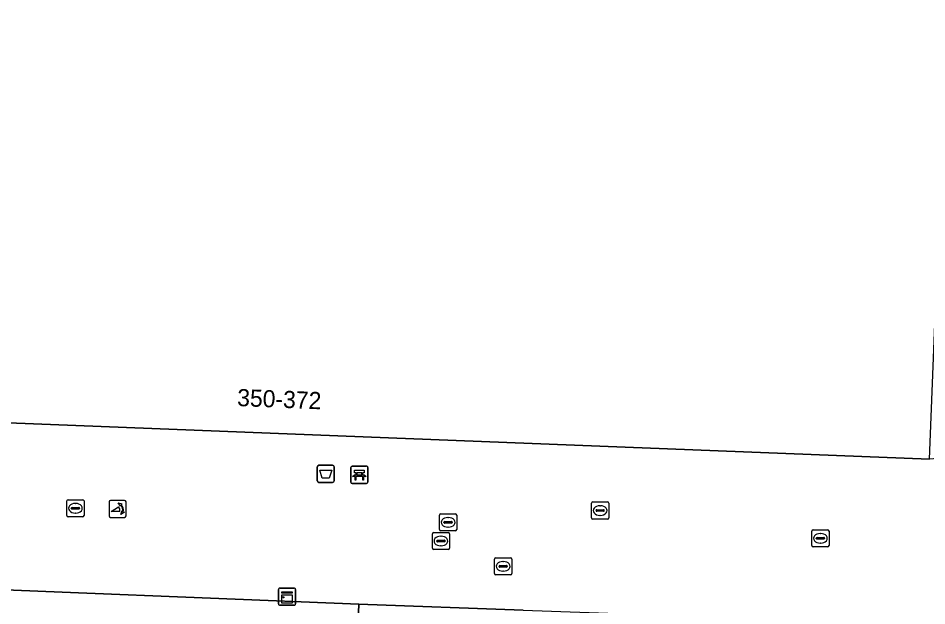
# Model space of a CAD drawing. Extents: x 160888 to 161385, y 386490 to 386908.
# Drawn here: x 161141.4 to 161194.4, y 386833.9 to 386868.1 of the extents above; entities that cross this region are included whole.
import ezdxf

# ---------------------------------------------------------------- set-up
doc = ezdxf.new("R2010")
doc.units = 0
for name, color, linetype in [('IMGEO_Afvalbak', 7, 'Continuous'), ('IMGEO_Bank', 7, 'Continuous'), ('IMGEO_Brandkraan', 7, 'Continuous'), ('IMGEO_Kast', 7, 'Continuous'), ('IMGEO_Kolk', 7, 'Continuous'), ('IMGEO_Pand', 7, 'Continuous'), ('IMGEO_Pand_nummerreeks', 7, 'Continuous'), ('IMGEO_Poller', 7, 'Continuous'), ('IMGEO_Rioolput', 7, 'Continuous'), ('IMGEO_Voetgangersgebied_open', 7, 'Continuous'), ('IMGEO_Voetpad_open', 7, 'Continuous')]:
    doc.layers.add(name, color=color, linetype=linetype)

msp = doc.modelspace()

# ---------------------------------------------------------------- linework, layer by layer
at = {"layer": 'IMGEO_Afvalbak'}
for p, q in [((161158.851, 386841.169), (161158.851, 386841.969)), ((161158.851, 386841.969), (161158.851, 386841.169)), ((161158.951, 386842.069), (161159.741, 386842.069)), ((161159.741, 386842.069), (161158.951, 386842.069)), ((161159.841, 386841.969), (161159.841, 386841.169)), ((161159.841, 386841.169), (161159.841, 386841.969)), ((161159.741, 386841.069), (161158.951, 386841.069)), ((161158.951, 386841.069), (161159.741, 386841.069))]:
    msp.add_line(p, q, dxfattribs=at)
msp.add_lwpolyline([(161158.994, 386841.783), (161159.698, 386841.783), (161159.549, 386841.313), (161159.143, 386841.313), (161158.994, 386841.783)], dxfattribs=at)
for centre, start, end in [((161158.951, 386841.969), 90, 180), ((161158.951, 386841.969), 90, 180), ((161159.741, 386841.969), 0, 90), ((161159.741, 386841.969), 360, 90), ((161158.951, 386841.169), 180, 270), ((161158.951, 386841.169), 180, 270), ((161159.741, 386841.169), 270, 0), ((161159.741, 386841.169), 270, 0)]:
    msp.add_arc(centre, 0.1, start, end, dxfattribs=at)
at = {"layer": 'IMGEO_Bank'}
for p, q in [((161160.805, 386841.088), (161160.805, 386841.929)), ((161160.805, 386841.929), (161160.805, 386841.088)), ((161160.88, 386842.013), (161161.721, 386842.013)), ((161161.721, 386842.013), (161160.88, 386842.013)), ((161161.446, 386841.631), (161161.164, 386841.631)), ((161161.805, 386841.938), (161161.805, 386841.097)), ((161161.805, 386841.097), (161161.805, 386841.938)), ((161161.502, 386841.411), (161161.109, 386841.411)), ((161161.114, 386841.519), (161161.114, 386841.625)), ((161161.158, 386841.625), (161161.158, 386841.519)), ((161161.164, 386841.513), (161161.446, 386841.513)), ((161161.452, 386841.519), (161161.452, 386841.625)), ((161161.496, 386841.625), (161161.496, 386841.519)), ((161161.73, 386841.013), (161160.889, 386841.013)), ((161160.889, 386841.013), (161161.73, 386841.013))]:
    msp.add_line(p, q, dxfattribs=at)
for points in [[(161161.108, 386841.631), (161161.022, 386841.631), (161161.022, 386841.792), (161161.585, 386841.792), (161161.585, 386841.631), (161161.502, 386841.631)], [(161161.052, 386841.411), (161160.91, 386841.411), (161161.022, 386841.513), (161161.108, 386841.513)], [(161161.102, 386841.404), (161161.102, 386841.197), (161161.059, 386841.197), (161161.059, 386841.404)], [(161161.502, 386841.513), (161161.585, 386841.513), (161161.697, 386841.411), (161161.558, 386841.411)], [(161161.552, 386841.404), (161161.552, 386841.197), (161161.508, 386841.197), (161161.508, 386841.404)]]:
    msp.add_lwpolyline(points, dxfattribs=at)
for centre, radius, start, end in [((161160.883, 386841.935), 0.0779, 92.4484, 184.2845), ((161160.883, 386841.935), 0.0779, 92.4484, 184.2845), ((161161.107, 386841.624), 0.00671, 2.8957, 87.1043), ((161161.164, 386841.624), 0.00671, 92.8957, 177.1043), ((161161.446, 386841.624), 0.00671, 2.8957, 87.1043), ((161161.503, 386841.624), 0.00671, 92.8957, 177.1043), ((161161.727, 386841.935), 0.0779, 2.4484, 94.2845), ((161161.727, 386841.935), 0.0779, 2.4484, 94.2845), ((161161.052, 386841.404), 0.00671, 2.8957, 87.1043), ((161161.109, 386841.404), 0.00671, 92.8957, 177.1043), ((161161.107, 386841.52), 0.00671, 272.8957, 357.1043), ((161161.164, 386841.52), 0.00671, 182.8957, 267.1043), ((161161.446, 386841.52), 0.00671, 272.8957, 357.1043), ((161161.503, 386841.52), 0.00671, 182.8957, 267.1043), ((161161.501, 386841.404), 0.00671, 2.8957, 87.1043), ((161161.558, 386841.404), 0.00671, 92.8957, 177.1043), ((161160.883, 386841.091), 0.0779, 182.4484, 274.2845), ((161160.883, 386841.091), 0.0779, 182.4484, 274.2845), ((161161.727, 386841.091), 0.0779, 272.4484, 4.2845), ((161161.727, 386841.091), 0.0779, 272.4484, 4.2845)]:
    msp.add_arc(centre, radius, start, end, dxfattribs=at)
at = {"layer": 'IMGEO_Brandkraan'}
for p, q in [((161169.199, 386835.749), (161169.199, 386836.601)), ((161169.274, 386836.675), (161170.126, 386836.675)), ((161169.687, 386836.455), (161169.712, 386836.455)), ((161170.2, 386836.601), (161170.2, 386835.749)), ((161169.458, 386836.169), (161169.458, 386836.181)), ((161169.896, 386836.132), (161169.498, 386836.132)), ((161169.501, 386836.218), (161169.899, 386836.218)), ((161169.71, 386835.895), (161169.685, 386835.895)), ((161169.942, 386836.181), (161169.942, 386836.169)), ((161170.126, 386835.675), (161169.274, 386835.675))]:
    msp.add_line(p, q, dxfattribs=at)
for points in [[(161169.199, 386835.749), (161169.199, 386836.601)], [(161169.274, 386836.675), (161170.126, 386836.675)], [(161170.2, 386836.601), (161170.2, 386835.749)], [(161170.126, 386835.675), (161169.274, 386835.675)]]:
    msp.add_lwpolyline(points, dxfattribs=at)
for centre, radius, start, end in [((161169.276, 386836.599), 0.0765, 91.552, 178.448), ((161169.276, 386836.599), 0.0765, 91.552, 178.448), ((161170.124, 386836.599), 0.0765, 1.552, 88.448), ((161170.124, 386836.599), 0.0765, 1.552, 88.448), ((161169.498, 386836.178), 0.0403, 85.8775, 175.7526), ((161169.495, 386836.168), 0.0366, 178.938, 274.7102), ((161169.899, 386836.175), 0.043, 264.8664, 352.4533), ((161169.903, 386836.18), 0.0386, 1.7309, 96.639), ((161169.276, 386835.751), 0.0765, 181.552, 268.448), ((161169.276, 386835.751), 0.0765, 181.552, 268.448), ((161170.124, 386835.751), 0.0765, 271.552, 358.448), ((161170.124, 386835.751), 0.0765, 271.552, 358.448)]:
    msp.add_arc(centre, radius, start, end, dxfattribs=at)
for centre, major_axis, ratio, start_param, end_param in [((161169.686, 386836.175), (-0.387, 0.002), 0.722429, 4.712389, 7.853982), ((161169.711, 386836.175), (-0.39, 0.002), 0.717154, 1.570796, 4.712389)]:
    msp.add_ellipse(centre, major_axis=major_axis, ratio=ratio, start_param=start_param, end_param=end_param, dxfattribs=at)
at = {"layer": 'IMGEO_Kast'}
for p, q in [((161156.584, 386833.979), (161156.584, 386834.82)), ((161156.584, 386834.82), (161156.584, 386833.979)), ((161156.659, 386834.904), (161157.5, 386834.904)), ((161157.5, 386834.904), (161156.659, 386834.904)), ((161157.584, 386834.829), (161157.584, 386833.988)), ((161157.584, 386833.988), (161157.584, 386834.829)), ((161157.509, 386833.904), (161156.668, 386833.904)), ((161156.668, 386833.904), (161157.509, 386833.904))]:
    msp.add_line(p, q, dxfattribs=at)
for points in [[(161156.779, 386834.694), (161157.379, 386834.694), (161157.379, 386834.609), (161156.779, 386834.609), (161156.779, 386834.694)], [(161156.779, 386834.519), (161157.379, 386834.519), (161157.379, 386834.03), (161156.779, 386834.03), (161156.779, 386834.519)]]:
    msp.add_lwpolyline(points, dxfattribs=at)
msp.add_circle((161156.863, 386834.368), 0.0377, dxfattribs=at)
for centre, start, end in [((161156.662, 386834.826), 92.4484, 184.2845), ((161156.662, 386834.826), 92.4484, 184.2845), ((161157.506, 386834.826), 2.4484, 94.2845), ((161157.506, 386834.826), 2.4484, 94.2845), ((161156.662, 386833.982), 182.4484, 274.2845), ((161156.662, 386833.982), 182.4484, 274.2845), ((161157.506, 386833.982), 272.4484, 4.2845), ((161157.506, 386833.982), 272.4484, 4.2845)]:
    msp.add_arc(centre, 0.0779, start, end, dxfattribs=at)
at = {"layer": 'IMGEO_Kolk'}
for p, q in [((161144.311, 386840.06), (161145.163, 386840.06)), ((161144.236, 386839.134), (161144.236, 386839.986)), ((161144.495, 386839.554), (161144.495, 386839.566)), ((161144.933, 386839.517), (161144.535, 386839.517)), ((161144.538, 386839.603), (161144.936, 386839.603)), ((161144.724, 386839.84), (161144.749, 386839.84)), ((161144.979, 386839.566), (161144.979, 386839.554)), ((161145.237, 386839.986), (161145.237, 386839.134)), ((161145.163, 386839.06), (161144.311, 386839.06)), ((161144.747, 386839.28), (161144.722, 386839.28)), ((161165.987, 386838.316), (161165.987, 386839.168)), ((161166.062, 386839.242), (161166.914, 386839.242)), ((161166.475, 386839.022), (161166.5, 386839.022)), ((161166.988, 386839.168), (161166.988, 386838.316)), ((161166.246, 386838.736), (161166.246, 386838.748)), ((161166.684, 386838.699), (161166.286, 386838.699)), ((161166.289, 386838.785), (161166.687, 386838.785)), ((161166.498, 386838.462), (161166.473, 386838.462)), ((161166.73, 386838.748), (161166.73, 386838.736)), ((161166.914, 386838.242), (161166.062, 386838.242)), ((161187.716, 386837.383), (161187.716, 386838.235)), ((161187.791, 386838.309), (161188.643, 386838.309)), ((161188.204, 386838.089), (161188.229, 386838.089)), ((161188.717, 386838.235), (161188.717, 386837.383)), ((161187.975, 386837.803), (161187.975, 386837.815)), ((161188.413, 386837.766), (161188.015, 386837.766)), ((161188.018, 386837.852), (161188.416, 386837.852)), ((161188.227, 386837.529), (161188.202, 386837.529)), ((161188.459, 386837.815), (161188.459, 386837.803)), ((161188.643, 386837.309), (161187.791, 386837.309))]:
    msp.add_line(p, q, dxfattribs=at)
for points in [[(161144.311, 386840.06), (161145.163, 386840.06)], [(161144.236, 386839.134), (161144.236, 386839.986)], [(161145.237, 386839.986), (161145.237, 386839.134)], [(161145.163, 386839.06), (161144.311, 386839.06)], [(161165.987, 386838.316), (161165.987, 386839.168)], [(161166.062, 386839.242), (161166.914, 386839.242)], [(161166.988, 386839.168), (161166.988, 386838.316)], [(161166.914, 386838.242), (161166.062, 386838.242)], [(161187.716, 386837.383), (161187.716, 386838.235)], [(161187.791, 386838.309), (161188.643, 386838.309)], [(161188.717, 386838.235), (161188.717, 386837.383)], [(161188.643, 386837.309), (161187.791, 386837.309)]]:
    msp.add_lwpolyline(points, dxfattribs=at)
for centre, radius, start, end in [((161144.313, 386839.984), 0.0765, 91.552, 178.448), ((161144.313, 386839.984), 0.0765, 91.552, 178.448), ((161145.161, 386839.984), 0.0765, 1.552, 88.448), ((161145.161, 386839.984), 0.0765, 1.552, 88.448), ((161144.535, 386839.563), 0.0403, 85.8775, 175.7526), ((161144.532, 386839.553), 0.0366, 178.938, 274.7102), ((161144.936, 386839.56), 0.043, 264.8664, 352.4533), ((161144.94, 386839.565), 0.0386, 1.7309, 96.639), ((161144.313, 386839.136), 0.0765, 181.552, 268.448), ((161144.313, 386839.136), 0.0765, 181.552, 268.448), ((161145.161, 386839.136), 0.0765, 271.552, 358.448), ((161145.161, 386839.136), 0.0765, 271.552, 358.448), ((161166.064, 386839.166), 0.0765, 91.552, 178.448), ((161166.064, 386839.166), 0.0765, 91.552, 178.448), ((161166.912, 386839.166), 0.0765, 1.552, 88.448), ((161166.912, 386839.166), 0.0765, 1.552, 88.448), ((161166.286, 386838.745), 0.0403, 85.8775, 175.7526), ((161166.283, 386838.735), 0.0366, 178.938, 274.7102), ((161166.687, 386838.742), 0.043, 264.8664, 352.4533), ((161166.691, 386838.747), 0.0386, 1.7309, 96.639), ((161166.064, 386838.318), 0.0765, 181.552, 268.448), ((161166.064, 386838.318), 0.0765, 181.552, 268.448), ((161166.912, 386838.318), 0.0765, 271.552, 358.448), ((161166.912, 386838.318), 0.0765, 271.552, 358.448), ((161187.793, 386838.233), 0.0765, 91.552, 178.448), ((161187.793, 386838.233), 0.0765, 91.552, 178.448), ((161188.641, 386838.233), 0.0765, 1.552, 88.448), ((161188.641, 386838.233), 0.0765, 1.552, 88.448), ((161188.015, 386837.812), 0.0403, 85.8775, 175.7526), ((161188.012, 386837.802), 0.0366, 178.938, 274.7102), ((161188.416, 386837.809), 0.043, 264.8664, 352.4533), ((161188.42, 386837.814), 0.0386, 1.7309, 96.639), ((161187.793, 386837.385), 0.0765, 181.552, 268.448), ((161187.793, 386837.385), 0.0765, 181.552, 268.448), ((161188.641, 386837.385), 0.0765, 271.552, 358.448), ((161188.641, 386837.385), 0.0765, 271.552, 358.448)]:
    msp.add_arc(centre, radius, start, end, dxfattribs=at)
for centre, major_axis, ratio, start_param, end_param in [((161144.723, 386839.56), (-0.387, 0.002), 0.722429, 4.712389, 7.853982), ((161144.748, 386839.56), (-0.39, 0.002), 0.717154, 1.570796, 4.712389), ((161166.474, 386838.742), (-0.387, 0.002), 0.722429, 4.712389, 7.853982), ((161166.499, 386838.742), (-0.39, 0.002), 0.717154, 1.570796, 4.712389), ((161188.203, 386837.809), (-0.387, 0.002), 0.722429, 4.712389, 7.853982), ((161188.228, 386837.809), (-0.39, 0.002), 0.717154, 1.570796, 4.712389)]:
    msp.add_ellipse(centre, major_axis=major_axis, ratio=ratio, start_param=start_param, end_param=end_param, dxfattribs=at)
at = {"layer": 'IMGEO_Pand'}
for points in [[(161120.067, 386845.369), (161194.586, 386842.427), (161196.377, 386887.78), (161196.381, 386887.886), (161196.395, 386888.23), (161188.186, 386888.554), (161178.427, 386888.94), (161127.058, 386890.969), (161126.941, 386888.577), (161126.862, 386886.972), (161123.715, 386887.092), (161123.545, 386882.788), (161121.567, 386882.869), (161121.073, 386870.746), (161120.711, 386870.76), (161120.682, 386870.014), (161121.042, 386870), (161120.551, 386857.609)], [(161139.487, 386830.001), (161139.114, 386820.799), (161139.102, 386820.494), (161138.818, 386813.477), (161138.527, 386806.308), (161138.037, 386794.207), (161137.648, 386784.596), (161137.363, 386777.579), (161137.063, 386770.156), (161136.569, 386757.969), (161156.498, 386757.182), (161158.228, 386758.915), (161158.648, 386769.233), (161158.95, 386776.656), (161159.236, 386783.673), (161159.627, 386793.285), (161160.119, 386805.384), (161160.411, 386812.554), (161160.709, 386819.875), (161161.282, 386833.963), (161143.958, 386834.674), (161139.684, 386834.849)]]:
    msp.add_lwpolyline(points, close=True, dxfattribs=at)
at = {"layer": 'IMGEO_Poller'}
for p, q in [((161146.698, 386839.927), (161146.698, 386839.12)), ((161146.698, 386839.927), (161146.698, 386839.12)), ((161147.6, 386840.022), (161146.792, 386840.022)), ((161147.6, 386840.022), (161146.792, 386840.022)), ((161147.694, 386839.12), (161147.694, 386839.927)), ((161147.694, 386839.12), (161147.694, 386839.927)), ((161146.792, 386839.025), (161147.6, 386839.025)), ((161146.792, 386839.025), (161147.6, 386839.025))]:
    msp.add_line(p, q, dxfattribs=at)
for points in [[(161147.333, 386839.378), (161146.82, 386839.378), (161147.25, 386839.653)], [(161147.377, 386839.751), (161147.365, 386839.678), (161147.24, 386839.883)], [(161147.24, 386839.883), (161147.471, 386839.817), (161147.4, 386839.785)], [(161147.393, 386839.206), (161147.459, 386839.437), (161147.489, 386839.369)], [(161147.525, 386839.342), (161147.597, 386839.331), (161147.393, 386839.206)]]:
    msp.add_lwpolyline(points, dxfattribs=at)
for centre, radius, start, end in [((161146.792, 386839.927), 0.0946, 90, 180), ((161146.792, 386839.927), 0.0946, 90, 180), ((161147.005, 386839.428), 0.332, 351.3247, 42.4854), ((161147.019, 386839.438), 0.476, 351.7527, 41.1691), ((161147.019, 386839.438), 0.516, 349.3569, 42.2912), ((161147.6, 386839.927), 0.0946, 0, 90), ((161147.6, 386839.927), 0.0946, 0, 90), ((161146.792, 386839.12), 0.0946, 180, 270), ((161146.792, 386839.12), 0.0946, 180, 270), ((161147.6, 386839.12), 0.0946, 270, 0), ((161147.6, 386839.12), 0.0946, 270, 0)]:
    msp.add_arc(centre, radius, start, end, dxfattribs=at)
at = {"layer": 'IMGEO_Rioolput'}
for p, q in [((161174.859, 386839.002), (161174.859, 386839.854)), ((161174.934, 386839.928), (161175.786, 386839.928)), ((161175.347, 386839.708), (161175.372, 386839.708)), ((161175.86, 386839.854), (161175.86, 386839.002)), ((161175.118, 386839.422), (161175.118, 386839.434)), ((161175.556, 386839.385), (161175.158, 386839.385)), ((161175.161, 386839.471), (161175.559, 386839.471)), ((161175.37, 386839.148), (161175.345, 386839.148)), ((161175.602, 386839.434), (161175.602, 386839.422)), ((161175.786, 386838.928), (161174.934, 386838.928)), ((161165.566, 386837.225), (161165.566, 386838.077)), ((161165.641, 386838.151), (161166.493, 386838.151)), ((161166.054, 386837.931), (161166.079, 386837.931)), ((161166.567, 386838.077), (161166.567, 386837.225)), ((161165.825, 386837.645), (161165.825, 386837.657)), ((161166.263, 386837.608), (161165.865, 386837.608)), ((161165.868, 386837.694), (161166.266, 386837.694)), ((161166.309, 386837.657), (161166.309, 386837.645)), ((161166.493, 386837.151), (161165.641, 386837.151)), ((161166.077, 386837.371), (161166.052, 386837.371))]:
    msp.add_line(p, q, dxfattribs=at)
for points in [[(161174.859, 386839.002), (161174.859, 386839.854)], [(161174.934, 386839.928), (161175.786, 386839.928)], [(161175.86, 386839.854), (161175.86, 386839.002)], [(161175.786, 386838.928), (161174.934, 386838.928)], [(161165.566, 386837.225), (161165.566, 386838.077)], [(161165.641, 386838.151), (161166.493, 386838.151)], [(161166.567, 386838.077), (161166.567, 386837.225)], [(161166.493, 386837.151), (161165.641, 386837.151)]]:
    msp.add_lwpolyline(points, dxfattribs=at)
for centre, radius, start, end in [((161174.936, 386839.852), 0.0765, 91.552, 178.448), ((161174.936, 386839.852), 0.0765, 91.552, 178.448), ((161175.784, 386839.852), 0.0765, 1.552, 88.448), ((161175.784, 386839.852), 0.0765, 1.552, 88.448), ((161174.936, 386839.004), 0.0765, 181.552, 268.448), ((161174.936, 386839.004), 0.0765, 181.552, 268.448), ((161175.158, 386839.431), 0.0403, 85.8775, 175.7526), ((161175.155, 386839.421), 0.0366, 178.938, 274.7102), ((161175.559, 386839.428), 0.043, 264.8664, 352.4533), ((161175.563, 386839.433), 0.0386, 1.7309, 96.639), ((161175.784, 386839.004), 0.0765, 271.552, 358.448), ((161175.784, 386839.004), 0.0765, 271.552, 358.448), ((161165.643, 386838.075), 0.0765, 91.552, 178.448), ((161165.643, 386838.075), 0.0765, 91.552, 178.448), ((161166.491, 386838.075), 0.0765, 1.552, 88.448), ((161166.491, 386838.075), 0.0765, 1.552, 88.448), ((161165.865, 386837.654), 0.0403, 85.8775, 175.7526), ((161165.862, 386837.644), 0.0366, 178.938, 274.7102), ((161166.266, 386837.651), 0.043, 264.8664, 352.4533), ((161166.27, 386837.656), 0.0386, 1.7309, 96.639), ((161165.643, 386837.227), 0.0765, 181.552, 268.448), ((161165.643, 386837.227), 0.0765, 181.552, 268.448), ((161166.491, 386837.227), 0.0765, 271.552, 358.448), ((161166.491, 386837.227), 0.0765, 271.552, 358.448)]:
    msp.add_arc(centre, radius, start, end, dxfattribs=at)
for centre, major_axis, ratio, start_param, end_param in [((161175.346, 386839.428), (-0.387, 0.002), 0.722429, 4.712389, 7.853982), ((161175.371, 386839.428), (-0.39, 0.002), 0.717154, 1.570796, 4.712389), ((161166.053, 386837.651), (-0.387, 0.002), 0.722429, 4.712389, 7.853982), ((161166.078, 386837.651), (-0.39, 0.002), 0.717154, 1.570796, 4.712389)]:
    msp.add_ellipse(centre, major_axis=major_axis, ratio=ratio, start_param=start_param, end_param=end_param, dxfattribs=at)
at = {"layer": 'IMGEO_Voetgangersgebied_open'}
msp.add_lwpolyline([(161128.442, 386835.301), (161139.684, 386834.849), (161143.958, 386834.674), (161161.282, 386833.963), (161170.867, 386833.628), (161190.117, 386832.93), (161199.627, 386832.585), (161199.621, 386832.448), (161201.804, 386832.359), (161216.339, 386831.766), (161223.504, 386831.473), (161238.036, 386830.88), (161252.467, 386830.291), (161259.736, 386829.994), (161269.188, 386829.608), (161281.723, 386829.096), (161281.825, 386831.496), (161282.087, 386837.641), (161282.13, 386838.652), (161282.19, 386840.045), (161203.707, 386843.159), (161196.993, 386842.62), (161194.586, 386842.427), (161120.067, 386845.369)], dxfattribs=at)
at = {"layer": 'IMGEO_Voetpad_open'}
msp.add_lwpolyline([(161170.867, 386833.628), (161161.282, 386833.963), (161160.709, 386819.875)], dxfattribs=at)

# ---------------------------------------------------------------- texts
at = {"layer": 'IMGEO_Pand_nummerreeks'}
msp.add_text('350-372', height=1, rotation=357.7391, dxfattribs=at).set_placement((161154.163, 386845.524))

doc.saveas('drawing.dxf')
